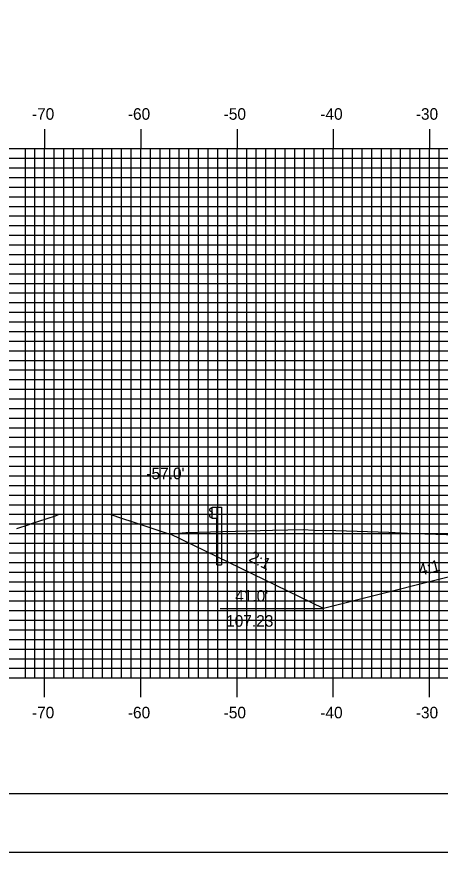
# Model space of a CAD drawing. Extents: x 1685192 to 1685536, y 461260 to 461480.
# Drawn here: x 1685285.3 to 1685329.3, y 461260 to 461346.8 of the extents above; entities that cross this region are included whole.
import ezdxf

# ---------------------------------------------------------------- set-up
doc = ezdxf.new("R2010")
doc.units = 0
for name, color, linetype in [('ANNOTATION', 7, 'Continuous'), ('BORDER', 7, 'Continuous'), ('D_Roadway_SlopeLines', 7, 'Continuous'), ('D_Text_Standard', 7, 'Continuous'), ('H_V ANNOTATION', 7, 'Continuous'), ('M_Roadway_Centerline', 7, 'Continuous'), ('MAJOR', 7, 'Continuous'), ('MINOR', 7, 'Continuous'), ('PDRAIN', 7, 'Continuous'), ('PLOT BOUNDARY', 7, 'Continuous'), ('S_Guardrail_Beam', 7, 'Continuous'), ('S_Roadway_Centerline', 7, 'Continuous')]:
    doc.layers.add(name, color=color, linetype=linetype)

msp = doc.modelspace()

# ---------------------------------------------------------------- linework, layer by layer
at = {"layer": 'BORDER'}
msp.add_lwpolyline([(1685208.629, 461266.072), (1685528.629, 461266.072), (1685528.629, 461476.072), (1685208.629, 461476.072)], close=True, dxfattribs=at)
at = {"layer": 'D_Roadway_SlopeLines'}
msp.add_line((1685317.201, 461285.302), (1685301.228, 461293.044), dxfattribs=at)
msp.add_lwpolyline([(1685340.229, 461291.059), (1685317.201, 461285.302)], dxfattribs=at)
at = {"layer": 'MAJOR'}
for p, q in [((1685288.229, 461335.076), (1685288.229, 461333.072)), ((1685298.229, 461335.076), (1685298.229, 461333.072)), ((1685308.229, 461335.076), (1685308.229, 461333.072)), ((1685318.229, 461335.076), (1685318.229, 461333.072)), ((1685328.229, 461335.076), (1685328.229, 461333.072)), ((1685218.229, 461333.072), (1685498.229, 461333.072)), ((1685218.229, 461333.072), (1685498.229, 461333.072)), ((1685288.229, 461278.072), (1685288.229, 461333.072)), ((1685298.229, 461278.072), (1685298.229, 461333.072)), ((1685308.229, 461278.072), (1685308.229, 461333.072)), ((1685318.229, 461278.072), (1685318.229, 461333.072)), ((1685328.229, 461278.072), (1685328.229, 461333.072)), ((1685218.229, 461328.072), (1685498.229, 461328.072)), ((1685218.229, 461323.072), (1685498.229, 461323.072)), ((1685218.229, 461318.072), (1685498.229, 461318.072)), ((1685218.229, 461313.072), (1685498.229, 461313.072)), ((1685218.229, 461308.072), (1685498.229, 461308.072)), ((1685218.229, 461303.072), (1685498.229, 461303.072)), ((1685218.229, 461298.072), (1685498.229, 461298.072)), ((1685218.229, 461293.072), (1685498.229, 461293.072)), ((1685218.229, 461288.072), (1685498.229, 461288.072)), ((1685218.229, 461283.072), (1685498.229, 461283.072)), ((1685218.229, 461278.072), (1685498.229, 461278.072)), ((1685218.229, 461278.072), (1685498.229, 461278.072)), ((1685288.229, 461276.068), (1685288.229, 461278.072)), ((1685298.229, 461276.068), (1685298.229, 461278.072)), ((1685308.229, 461276.068), (1685308.229, 461278.072)), ((1685318.229, 461276.068), (1685318.229, 461278.072)), ((1685328.229, 461276.068), (1685328.229, 461278.072))]:
    msp.add_line(p, q, dxfattribs=at)
at = {"layer": 'MINOR'}
for p, q in [((1685286.229, 461278.072), (1685286.229, 461333.072)), ((1685287.229, 461278.072), (1685287.229, 461333.072)), ((1685289.229, 461278.072), (1685289.229, 461333.072)), ((1685290.229, 461278.072), (1685290.229, 461333.072)), ((1685291.229, 461278.072), (1685291.229, 461333.072)), ((1685292.229, 461278.072), (1685292.229, 461333.072)), ((1685293.229, 461278.072), (1685293.229, 461333.072)), ((1685294.229, 461278.072), (1685294.229, 461333.072)), ((1685295.229, 461278.072), (1685295.229, 461333.072)), ((1685296.229, 461278.072), (1685296.229, 461333.072)), ((1685297.229, 461278.072), (1685297.229, 461333.072)), ((1685299.229, 461278.072), (1685299.229, 461333.072)), ((1685300.229, 461278.072), (1685300.229, 461333.072)), ((1685301.229, 461278.072), (1685301.229, 461333.072)), ((1685302.229, 461278.072), (1685302.229, 461333.072)), ((1685303.229, 461278.072), (1685303.229, 461333.072)), ((1685304.229, 461278.072), (1685304.229, 461333.072)), ((1685305.229, 461278.072), (1685305.229, 461333.072)), ((1685306.229, 461278.072), (1685306.229, 461333.072)), ((1685307.229, 461278.072), (1685307.229, 461333.072)), ((1685309.229, 461278.072), (1685309.229, 461333.072)), ((1685310.229, 461278.072), (1685310.229, 461333.072)), ((1685311.229, 461278.072), (1685311.229, 461333.072)), ((1685312.229, 461278.072), (1685312.229, 461333.072)), ((1685313.229, 461278.072), (1685313.229, 461333.072)), ((1685314.229, 461278.072), (1685314.229, 461333.072)), ((1685315.229, 461278.072), (1685315.229, 461333.072)), ((1685316.229, 461278.072), (1685316.229, 461333.072)), ((1685317.229, 461278.072), (1685317.229, 461333.072)), ((1685319.229, 461278.072), (1685319.229, 461333.072)), ((1685320.229, 461278.072), (1685320.229, 461333.072)), ((1685321.229, 461278.072), (1685321.229, 461333.072)), ((1685322.229, 461278.072), (1685322.229, 461333.072)), ((1685323.229, 461278.072), (1685323.229, 461333.072)), ((1685324.229, 461278.072), (1685324.229, 461333.072)), ((1685325.229, 461278.072), (1685325.229, 461333.072)), ((1685326.229, 461278.072), (1685326.229, 461333.072)), ((1685327.229, 461278.072), (1685327.229, 461333.072)), ((1685329.229, 461278.072), (1685329.229, 461333.072)), ((1685218.229, 461332.072), (1685498.229, 461332.072)), ((1685218.229, 461331.072), (1685498.229, 461331.072)), ((1685218.229, 461330.072), (1685498.229, 461330.072)), ((1685218.229, 461329.072), (1685498.229, 461329.072)), ((1685218.229, 461327.072), (1685498.229, 461327.072)), ((1685218.229, 461326.072), (1685498.229, 461326.072)), ((1685218.229, 461325.072), (1685498.229, 461325.072)), ((1685218.229, 461324.072), (1685498.229, 461324.072)), ((1685218.229, 461322.072), (1685498.229, 461322.072)), ((1685218.229, 461321.072), (1685498.229, 461321.072)), ((1685218.229, 461320.072), (1685498.229, 461320.072)), ((1685218.229, 461319.072), (1685498.229, 461319.072)), ((1685218.229, 461317.072), (1685498.229, 461317.072)), ((1685218.229, 461316.072), (1685498.229, 461316.072)), ((1685218.229, 461315.072), (1685498.229, 461315.072)), ((1685218.229, 461314.072), (1685498.229, 461314.072)), ((1685218.229, 461312.072), (1685498.229, 461312.072)), ((1685218.229, 461311.072), (1685498.229, 461311.072)), ((1685218.229, 461310.072), (1685498.229, 461310.072)), ((1685218.229, 461309.072), (1685498.229, 461309.072)), ((1685218.229, 461307.072), (1685498.229, 461307.072)), ((1685218.229, 461306.072), (1685498.229, 461306.072)), ((1685218.229, 461305.072), (1685498.229, 461305.072)), ((1685218.229, 461304.072), (1685498.229, 461304.072)), ((1685218.229, 461302.072), (1685498.229, 461302.072)), ((1685218.229, 461301.072), (1685498.229, 461301.072)), ((1685218.229, 461300.072), (1685498.229, 461300.072)), ((1685218.229, 461299.072), (1685498.229, 461299.072)), ((1685218.229, 461297.072), (1685498.229, 461297.072)), ((1685218.229, 461296.072), (1685498.229, 461296.072)), ((1685218.229, 461295.072), (1685498.229, 461295.072)), ((1685218.229, 461294.072), (1685498.229, 461294.072)), ((1685218.229, 461292.072), (1685498.229, 461292.072)), ((1685218.229, 461291.072), (1685498.229, 461291.072)), ((1685218.229, 461290.072), (1685498.229, 461290.072)), ((1685218.229, 461289.072), (1685498.229, 461289.072)), ((1685218.229, 461287.072), (1685498.229, 461287.072)), ((1685218.229, 461286.072), (1685498.229, 461286.072)), ((1685218.229, 461285.072), (1685498.229, 461285.072)), ((1685218.229, 461284.072), (1685498.229, 461284.072)), ((1685218.229, 461282.072), (1685498.229, 461282.072)), ((1685218.229, 461281.072), (1685498.229, 461281.072)), ((1685218.229, 461280.072), (1685498.229, 461280.072)), ((1685218.229, 461279.072), (1685498.229, 461279.072))]:
    msp.add_line(p, q, dxfattribs=at)
at = {"layer": 'PDRAIN'}
msp.add_line((1685306.478, 461285.302), (1685317.201, 461285.302), dxfattribs=at)
at = {"layer": 'PLOT BOUNDARY'}
msp.add_lwpolyline([(1685192.443, 461259.954), (1685532.443, 461259.954), (1685532.443, 461479.954), (1685192.443, 461479.954)], close=True, dxfattribs=at)
at = {"layer": 'S_Guardrail_Beam'}
for p, q in [((1685305.548, 461295.72), (1685305.405, 461295.62)), ((1685305.548, 461295.72), (1685305.405, 461295.62)), ((1685305.405, 461295.476), (1685305.6, 461295.34)), ((1685305.405, 461295.476), (1685305.6, 461295.34)), ((1685305.647, 461295.741), (1685305.565, 461295.726)), ((1685305.647, 461295.741), (1685305.565, 461295.726)), ((1685305.634, 461295.276), (1685305.634, 461295.185)), ((1685305.634, 461295.276), (1685305.634, 461295.185)), ((1685305.647, 461295.814), (1685306.136, 461295.814)), ((1685305.647, 461294.647), (1685305.647, 461295.814)), ((1685305.647, 461295.814), (1685306.136, 461295.814)), ((1685305.647, 461294.647), (1685305.647, 461295.814)), ((1685306.136, 461295.814), (1685306.628, 461295.814)), ((1685306.136, 461295.814), (1685306.136, 461294.647)), ((1685306.136, 461295.814), (1685306.628, 461295.814)), ((1685306.136, 461295.814), (1685306.136, 461294.647)), ((1685306.628, 461295.814), (1685306.628, 461289.814)), ((1685306.628, 461295.814), (1685306.628, 461289.814)), ((1685305.6, 461295.12), (1685305.405, 461294.984)), ((1685305.6, 461295.12), (1685305.405, 461294.984)), ((1685305.405, 461294.841), (1685305.548, 461294.741)), ((1685305.405, 461294.841), (1685305.548, 461294.741)), ((1685305.565, 461294.734), (1685305.647, 461294.72)), ((1685305.565, 461294.734), (1685305.647, 461294.72)), ((1685306.136, 461294.647), (1685305.647, 461294.647)), ((1685306.136, 461294.647), (1685305.647, 461294.647)), ((1685306.136, 461289.814), (1685306.136, 461294.647)), ((1685306.136, 461289.814), (1685306.136, 461294.647)), ((1685306.136, 461289.814), (1685306.628, 461289.814)), ((1685306.136, 461289.814), (1685306.628, 461289.814))]:
    msp.add_line(p, q, dxfattribs=at)
for centre, major_axis, start_param, end_param in [((1685305.455, 461295.548), (-0.0877, 0), 5.323254, 7.243116), ((1685305.455, 461295.548), (-0.0877, 0), 5.323254, 7.243116), ((1685305.572, 461295.686), (-0.0417, 0), 4.886922, 5.323254), ((1685305.572, 461295.686), (-0.0417, 0), 4.886922, 5.323254), ((1685305.555, 461295.276), (0.0789, 0), 0, 0.959931), ((1685305.555, 461295.276), (0.0789, 0), 0, 0.959931), ((1685305.455, 461294.913), (-0.0877, 0), 5.323254, 7.243116), ((1685305.455, 461294.913), (-0.0877, 0), 5.323254, 7.243116), ((1685305.572, 461294.775), (-0.0417, 0), 0.959931, 1.396263), ((1685305.572, 461294.775), (-0.0417, 0), 0.959931, 1.396263), ((1685305.555, 461295.185), (0.0789, 0), 5.323254, 6.283185), ((1685305.555, 461295.185), (0.0789, 0), 5.323254, 6.283185)]:
    msp.add_ellipse(centre, major_axis=major_axis, ratio=0.995501, start_param=start_param, end_param=end_param, dxfattribs=at)
at = {"layer": 'S_Roadway_Centerline'}
for points in [[(1685285.332, 461293.592), (1685286.61, 461294.016), (1685286.697, 461294.045), (1685286.778, 461294.072), (1685286.778, 461294.072), (1685286.778, 461294.072), (1685289.361, 461294.929), (1685289.509, 461294.978), (1685289.793, 461295.072), (1685289.867, 461295.072), (1685289.893, 461295.072), (1685290.437, 461295.072), (1685290.495, 461295.072), (1685294.918, 461295.072), (1685294.998, 461295.072), (1685295.018, 461295.072), (1685296.328, 461294.637), (1685297.299, 461294.315), (1685298.033, 461294.072), (1685298.033, 461294.072), (1685298.033, 461294.072), (1685300.925, 461293.112), (1685301.15, 461293.038), (1685301.151, 461293.038)], [(1685301.228, 461293.044), (1685302.158, 461293.115), (1685302.916, 461293.185), (1685311.913, 461293.418), (1685315.102, 461293.511), (1685316.189, 461293.425), (1685318.497, 461293.388), (1685323.994, 461293.213), (1685326.604, 461293.088), (1685331.136, 461292.928)]]:
    msp.add_lwpolyline(points, dxfattribs=at)

# ---------------------------------------------------------------- texts
at = {"layer": 'ANNOTATION'}
for s, rotation, p in [('2:1', 333.43495, (1685309.36, 461290.258)), ('4:1', 14.03624, (1685327.251, 461288.676))]:
    msp.add_text(s, height=1.2, rotation=rotation, dxfattribs=at).set_placement(p)
for s, p in [("41.0' ", (1685308.035, 461285.994)), ('107.23', (1685307.093, 461283.394))]:
    msp.add_text(s, height=1.2, dxfattribs=at).set_placement(p)
at = {"layer": 'D_Text_Standard'}
msp.add_text("-57.0'", height=1.2, dxfattribs=at).set_placement((1685298.804, 461298.722))
at = {"layer": 'H_V ANNOTATION'}
for s, p in [('-70', (1685286.913, 461336.072)), ('-60', (1685296.881, 461336.072)), ('-50', (1685306.838, 461336.072)), ('-40', (1685316.881, 461336.072)), ('-30', (1685326.806, 461336.072)), ('-70', (1685286.913, 461273.872)), ('-60', (1685296.881, 461273.872)), ('-50', (1685306.838, 461273.872)), ('-40', (1685316.881, 461273.872)), ('-30', (1685326.806, 461273.872))]:
    msp.add_text(s, height=1.2, dxfattribs=at).set_placement(p)
at = {"layer": 'M_Roadway_Centerline'}
for s, p in [('C', (1685323.989, 461293.213)), ('L', (1685323.994, 461293.206))]:
    msp.add_text(s, height=0.0146, dxfattribs=at).set_placement(p)

doc.saveas('drawing.dxf')
